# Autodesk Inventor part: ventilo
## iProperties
Created: 2011-01
Part Number: ventilo
Document SubType Name: Modeling
Designer: eric
Density: 1 g/cm^3
Mass: 81.1548 g
Surface Area: 299.57 cm^2
Volume: 81.1548 cm^3
Author: eric
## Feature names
1. Base1
